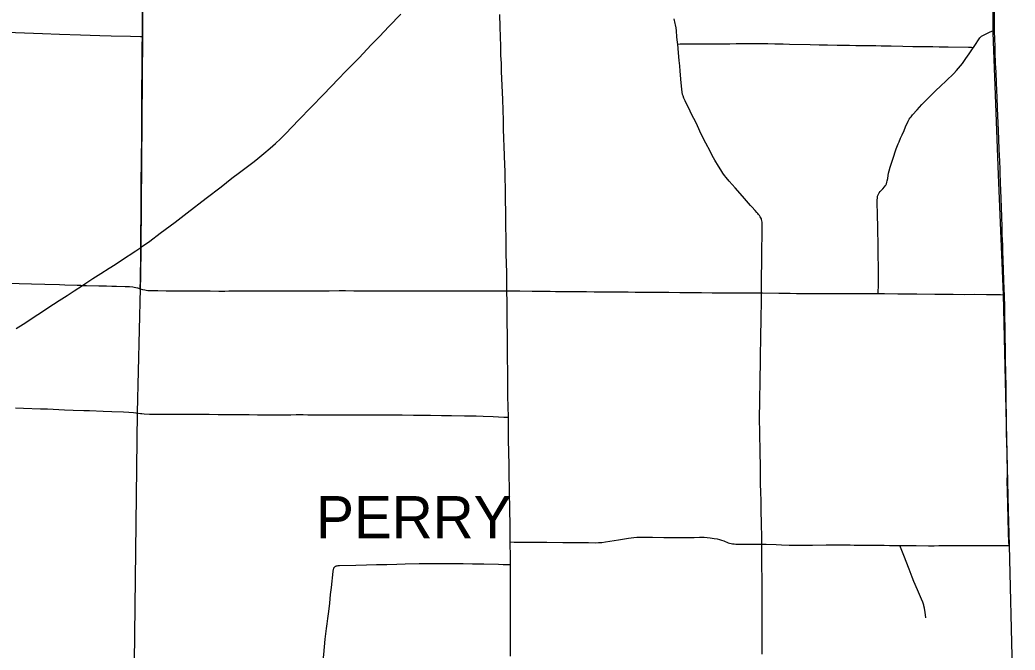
# Model space of a CAD drawing. Extents: x 1815539 to 1947826, y 273303 to 993194.
# Drawn here: x 1913070 to 1934195, y 939932 to 953318 of the extents above; entities that cross this region are included whole.
import ezdxf

# ---------------------------------------------------------------- set-up
doc = ezdxf.new("R2010")
doc.units = 0
for name, color, linetype in [('GM_X_County', 7, 'Continuous'), ('GM_X_County_Road', 7, 'Continuous'), ('GM_X_State_Route', 7, 'Continuous'), ('GM_X_Township', 7, 'Continuous'), ('GM_X_Township_Road', 7, 'Continuous'), ('GM_X_Township_Text', 7, 'Continuous'), ('GM_X_US_Route', 7, 'Continuous')]:
    doc.layers.add(name, color=color, linetype=linetype)

msp = doc.modelspace()

# ---------------------------------------------------------------- linework, layer by layer
at = {"layer": 'GM_X_County'}
msp.add_lwpolyline([(1928357, 965797), (1928425, 962614), (1928467, 960653), (1930020, 960674), (1933801, 960656), (1933723, 955963), (1933713, 955812), (1933717, 954747), (1933720, 953054), (1933836, 950026), (1933939, 947488), (1934048, 942901), (1934067, 942157), (1934195, 936859)], dxfattribs=at)
at = {"layer": 'GM_X_County_Road'}
for points in [[(1915670, 952967), (1915670, 952983), (1915670, 953098), (1915673, 953312), (1915675, 953525), (1915676, 953755), (1915681, 954215), (1915682, 954412), (1915683, 954576), (1915683, 954707), (1915686, 955036), (1915690, 955266), (1915691, 955430), (1915693, 955551), (1915693, 955599)], [(1915635, 948484), (1915639, 948648), (1915640, 948829), (1915642, 949108), (1915644, 949371), (1915645, 949568), (1915644, 949699), (1915644, 949830), (1915646, 950011), (1915648, 950159), (1915649, 950274), (1915653, 950405), (1915655, 950783), (1915656, 951013), (1915656, 951259), (1915658, 951456), (1915659, 951670), (1915660, 951883), (1915663, 952212), (1915665, 952474), (1915667, 952753), (1915670, 952967)], [(1915625, 947609), (1915626, 947637), (1915627, 947775), (1915630, 947972), (1915635, 948153), (1915637, 948269), (1915636, 948351), (1915636, 948466), (1915635, 948484)], [(1910365, 947816), (1910498, 947813), (1910842, 947800), (1911137, 947790), (1911350, 947783), (1911580, 947775), (1911744, 947768), (1911941, 947760), (1912104, 947754), (1912301, 947748), (1912662, 947734), (1913055, 947722), (1913318, 947713), (1913597, 947703), (1913908, 947695), (1914023, 947692), (1914285, 947685), (1914367, 947681), (1914402, 947680)], [(1914402, 947680), (1914482, 947679), (1914744, 947673), (1914908, 947667), (1915023, 947663), (1915121, 947662), (1915302, 947656), (1915400, 947652), (1915466, 947647), (1915498, 947643), (1915531, 947637), (1915563, 947629), (1915625, 947609)], [(1915625, 947609), (1915673, 947595), (1915720, 947583), (1915752, 947577), (1915784, 947572), (1915833, 947569), (1915997, 947567), (1916177, 947565), (1916292, 947565), (1916390, 947564), (1916571, 947563), (1916669, 947562), (1916932, 947560), (1917112, 947560), (1917292, 947559), (1917423, 947559), (1917505, 947560), (1917604, 947562), (1917702, 947562), (1917800, 947561), (1917866, 947560), (1917931, 947560), (1918062, 947561), (1918111, 947561), (1918325, 947563), (1918407, 947563), (1918571, 947564), (1918685, 947563), (1918800, 947564), (1918882, 947564), (1919259, 947564), (1919358, 947564), (1919473, 947565), (1919554, 947565), (1919636, 947566), (1919850, 947567), (1919981, 947567), (1920161, 947566), (1920489, 947563), (1920637, 947565), (1920735, 947566), (1921063, 947564), (1921260, 947562), (1921408, 947564), (1921506, 947564), (1921621, 947562), (1921702, 947562), (1921816, 947562), (1921948, 947563), (1922128, 947563), (1922341, 947561), (1922456, 947562), (1922718, 947563), (1923047, 947563), (1923226, 947563), (1923372, 947561), (1923409, 947561)], [(1923409, 947561), (1923536, 947562), (1923684, 947562), (1923946, 947559), (1924077, 947557), (1924209, 947556), (1924323, 947554), (1924438, 947552), (1924569, 947552), (1924733, 947550), (1924799, 947550), (1924995, 947547), (1925094, 947546), (1925258, 947545), (1925405, 947544), (1925651, 947543), (1925815, 947540), (1925979, 947539), (1926127, 947537), (1926274, 947536), (1926389, 947536), (1926504, 947536), (1926652, 947533), (1926848, 947533), (1927078, 947531), (1927258, 947529), (1927390, 947527), (1927537, 947527), (1927767, 947524), (1927947, 947523), (1928029, 947523), (1928226, 947522), (1928603, 947519), (1928814, 947518)], [(1928814, 947518), (1928833, 947518), (1929178, 947515), (1929325, 947513), (1929424, 947512), (1929555, 947510), (1929653, 947510), (1929801, 947509), (1930080, 947506), (1930309, 947506), (1930555, 947507), (1930654, 947508), (1930851, 947509), (1931047, 947507), (1931244, 947506), (1931286, 947506)], [(1931286, 947506), (1931425, 947505), (1931704, 947502), (1931981, 947499), (1932112, 947499), (1932489, 947494), (1932882, 947492), (1933112, 947489), (1933341, 947490), (1933587, 947488), (1933882, 947482), (1933932, 947480), (1933967, 947479)]]:
    msp.add_lwpolyline(points, dxfattribs=at)
at = {"layer": 'GM_X_State_Route'}
for points in [[(1923416, 946828), (1923415, 946875), (1923414, 947039), (1923414, 947203), (1923412, 947367), (1923409, 947515), (1923409, 947561), (1923408, 947646), (1923406, 947777), (1923403, 947925), (1923399, 948171), (1923395, 948319), (1923393, 948466), (1923390, 948646), (1923386, 948974), (1923384, 949122), (1923382, 949286), (1923381, 949450), (1923375, 949745), (1923372, 949958), (1923368, 950089), (1923358, 950417), (1923350, 950647), (1923345, 950778), (1923338, 951024), (1923333, 951188), (1923326, 951401), (1923318, 951630), (1923295, 952220), (1923290, 952401), (1923282, 952565), (1923276, 952761), (1923269, 952958), (1923263, 953171), (1923256, 953433)], [(1923442, 944632), (1923443, 944695), (1923440, 944875), (1923440, 944880), (1923434, 945105), (1923431, 945318), (1923429, 945481), (1923427, 945662), (1923425, 945809), (1923425, 945941), (1923423, 946039), (1923422, 946170), (1923420, 946416), (1923417, 946695), (1923416, 946828)], [(1923486, 939807), (1923485, 940021), (1923485, 940168), (1923485, 940513), (1923485, 940660), (1923485, 940906), (1923484, 941152), (1923483, 941431), (1923483, 941611), (1923483, 941752), (1923482, 941923), (1923479, 942202), (1923478, 942230), (1923475, 942579), (1923468, 942924), (1923467, 943022), (1923466, 943186), (1923462, 943383), (1923457, 943629), (1923453, 943858), (1923448, 944137), (1923443, 944400), (1923442, 944596), (1923442, 944632)]]:
    msp.add_lwpolyline(points, dxfattribs=at)
at = {"layer": 'GM_X_Township'}
msp.add_lwpolyline([(1889423, 961536), (1894728, 961453), (1894730, 961440), (1894815, 961451), (1899962, 961375), (1907847, 961159), (1910485, 961083), (1915744, 960965), (1915744, 960672), (1915689, 955598), (1915669, 952972), (1915640, 948490), (1915630, 947868), (1915624, 947610), (1915561, 944982), (1915495, 939674)], dxfattribs=at)
at = {"layer": 'GM_X_Township_Road'}
for points in [[(1933760, 953098), (1933758, 953287), (1933757, 953402), (1933754, 953582), (1933754, 953664), (1933751, 953762), (1933744, 954041), (1933740, 954221), (1933734, 954451), (1933730, 954615), (1933723, 954828), (1933719, 954910), (1933717, 954972), (1933716, 955106), (1933717, 955171), (1933717, 955237), (1933721, 955434), (1933723, 955581), (1933729, 955762), (1933730, 955808)], [(1927033, 952806), (1927029, 952841), (1927018, 952955), (1927005, 953084), (1926998, 953149), (1926988, 953212), (1926982, 953243), (1926959, 953338)], [(1910427, 953140), (1910699, 953130), (1910977, 953122), (1911371, 953109), (1911699, 953099), (1911977, 953091), (1912600, 953066), (1912715, 953060), (1912977, 953051), (1913551, 953030), (1913911, 953017), (1914354, 953002), (1914764, 952989), (1915010, 952982), (1915420, 952971), (1915633, 952967), (1915670, 952967)], [(1933309, 952730), (1933356, 952799), (1933420, 952894), (1933449, 952934), (1933470, 952959), (1933482, 952970), (1933495, 952980), (1933509, 952989), (1933538, 953004), (1933568, 953017), (1933667, 953062), (1933720, 953083), (1933760, 953098)], [(1933879, 950068), (1933876, 950143), (1933869, 950324), (1933864, 950438), (1933859, 950569), (1933843, 950979), (1933824, 951438), (1933813, 951683), (1933808, 951814), (1933800, 951994), (1933791, 952190), (1933785, 952320), (1933782, 952369), (1933777, 952451), (1933774, 952566), (1933770, 952779), (1933766, 952894), (1933760, 953090), (1933760, 953098)], [(1927033, 952806), (1927089, 952808), (1927137, 952807), (1927388, 952808), (1927536, 952810), (1927651, 952810), (1927782, 952811), (1927929, 952811), (1928027, 952813), (1928142, 952813), (1928273, 952815), (1928584, 952818), (1928699, 952817), (1928945, 952814), (1929092, 952811), (1929273, 952807), (1929404, 952803), (1929846, 952797), (1930037, 952792), (1930216, 952787), (1930419, 952779), (1930534, 952779), (1930681, 952779), (1930812, 952777), (1930943, 952775), (1931091, 952773), (1931173, 952772), (1931238, 952771), (1931353, 952770), (1931467, 952767), (1931565, 952765), (1931811, 952761), (1932024, 952755), (1932204, 952754), (1932303, 952754), (1932450, 952751), (1932581, 952748), (1932777, 952747), (1933204, 952741), (1933253, 952738), (1933271, 952738), (1933309, 952730)], [(1928814, 947518), (1928814, 947608), (1928815, 947741), (1928815, 947883), (1928818, 948145), (1928821, 948458), (1928826, 948737), (1928828, 948868), (1928827, 948982), (1928824, 949021), (1928822, 949050), (1928815, 949079), (1928809, 949095), (1928800, 949112), (1928787, 949138), (1928767, 949164), (1928748, 949188), (1928732, 949207), (1928712, 949229), (1928676, 949272), (1928606, 949350), (1928582, 949377), (1928493, 949477), (1928407, 949575), (1928252, 949750), (1928126, 949891), (1928063, 949972), (1928029, 950015), (1927993, 950064), (1927947, 950132), (1927899, 950210), (1927824, 950339), (1927768, 950440), (1927723, 950527), (1927631, 950700), (1927534, 950890), (1927452, 951069), (1927402, 951172), (1927351, 951275), (1927299, 951377), (1927192, 951598), (1927165, 951658), (1927147, 951705), (1927138, 951737), (1927129, 951785), (1927120, 951850), (1927108, 951981), (1927085, 952226), (1927076, 952339), (1927066, 952453), (1927059, 952534), (1927041, 952713), (1927033, 952806)], [(1932614, 951913), (1932730, 952024), (1932895, 952183), (1932952, 952242), (1932996, 952291), (1933038, 952341), (1933077, 952394), (1933153, 952500), (1933217, 952596), (1933291, 952704), (1933309, 952730)], [(1931286, 947506), (1931289, 947548), (1931291, 947564), (1931296, 947646), (1931297, 947712), (1931294, 947794), (1931293, 947859), (1931294, 947925), (1931295, 947974), (1931296, 948022), (1931295, 948070), (1931295, 948086), (1931295, 948102), (1931294, 948119), (1931294, 948134), (1931291, 948247), (1931290, 948295), (1931289, 948344), (1931288, 948393), (1931286, 948541), (1931280, 948869), (1931274, 949230), (1931270, 949394), (1931270, 949492), (1931273, 949541), (1931278, 949573), (1931283, 949589), (1931289, 949604), (1931295, 949619), (1931303, 949633), (1931312, 949647), (1931331, 949673), (1931352, 949698), (1931387, 949733), (1931420, 949769), (1931440, 949795), (1931448, 949809), (1931463, 949839), (1931474, 949869), (1931483, 949901), (1931492, 949949), (1931502, 950014), (1931511, 950062), (1931522, 950110), (1931545, 950189), (1931602, 950360), (1931674, 950578), (1931712, 950686), (1931731, 950731), (1931766, 950805), (1931800, 950880), (1931838, 950970), (1931871, 951045), (1931926, 951164), (1931949, 951208), (1931967, 951235), (1931986, 951262), (1932018, 951299), (1932117, 951409), (1932215, 951519), (1932259, 951567), (1932329, 951636), (1932412, 951716), (1932529, 951831), (1932599, 951899), (1932614, 951913)], [(1933967, 947479), (1933963, 947588), (1933959, 947802), (1933952, 947998), (1933941, 948228), (1933938, 948392), (1933932, 948539), (1933927, 948637), (1933921, 948768), (1933918, 948915), (1933911, 949144), (1933905, 949324), (1933898, 949537), (1933892, 949684), (1933886, 949865), (1933879, 950068)], [(1928819, 942182), (1928819, 942189), (1928817, 942376), (1928813, 942573), (1928809, 942737), (1928808, 942786), (1928806, 942884), (1928806, 942966), (1928803, 943147), (1928800, 943245), (1928794, 943507), (1928792, 943638), (1928789, 943786), (1928788, 943851), (1928788, 943950), (1928787, 944015), (1928783, 944212), (1928782, 944310), (1928778, 944375), (1928774, 944556), (1928773, 944851), (1928773, 944982), (1928775, 945098), (1928778, 945293), (1928784, 945605), (1928786, 945752), (1928788, 945982), (1928789, 946146), (1928794, 946310), (1928795, 946441), (1928798, 946556), (1928800, 946703), (1928803, 946850), (1928807, 947063), (1928812, 947260), (1928814, 947489), (1928814, 947518)], [(1934066, 942151), (1934064, 942235), (1934056, 942413), (1934053, 942510), (1934052, 942559), (1934050, 942608), (1934049, 942641), (1934049, 942690), (1934048, 942738), (1934047, 942786), (1934046, 942849), (1934045, 942865), (1934044, 942881), (1934040, 942995), (1934039, 943044), (1934039, 943094), (1934036, 943241), (1934035, 943323), (1934030, 943504), (1934031, 943684), (1934026, 944094), (1934019, 944373), (1934016, 944521), (1934013, 944718), (1934010, 944849), (1934007, 945259), (1934003, 945571), (1934000, 945768), (1933993, 946162), (1933990, 946326), (1933985, 946588), (1933982, 946736), (1933981, 946851), (1933980, 946949), (1933975, 947212), (1933967, 947479)], [(1912974, 945078), (1913149, 945072), (1913510, 945059), (1913658, 945054), (1913773, 945051), (1914019, 945039), (1914200, 945032), (1914429, 945023), (1914544, 945019), (1914840, 945010), (1915021, 945002), (1915267, 944993), (1915382, 944987), (1915480, 944979), (1915529, 944973), (1915538, 944971)], [(1915538, 944971), (1915632, 944959)], [(1915632, 944959), (1915659, 944955), (1915708, 944951), (1915823, 944947), (1915970, 944946), (1916085, 944946), (1916232, 944946), (1916429, 944943), (1916659, 944942), (1916855, 944942), (1917085, 944941), (1917281, 944938), (1917445, 944937), (1917740, 944937), (1917937, 944935), (1918117, 944933), (1918281, 944932), (1918527, 944933), (1918675, 944933), (1918822, 944933), (1918937, 944934), (1919084, 944934), (1919183, 944932), (1919281, 944932), (1919412, 944931), (1919527, 944931), (1919674, 944929), (1919805, 944929), (1920018, 944929), (1920199, 944930), (1920362, 944930), (1920608, 944930), (1920723, 944931), (1920838, 944931), (1921018, 944927), (1921182, 944928), (1921428, 944924), (1921788, 944922), (1922018, 944917), (1922231, 944915), (1922510, 944910), (1922755, 944906), (1922903, 944903), (1923116, 944893), (1923345, 944883), (1923411, 944881), (1923440, 944880)], [(1923478, 942230), (1923563, 942227), (1923662, 942226), (1923810, 942227), (1923990, 942226), (1924122, 942224), (1924253, 942222), (1924598, 942221), (1924828, 942218), (1924992, 942216), (1925140, 942215), (1925288, 942213), (1925354, 942215), (1925420, 942221), (1925501, 942232), (1925777, 942275), (1925988, 942307), (1926102, 942323), (1926167, 942329), (1926233, 942331), (1926348, 942332), (1926495, 942329), (1926742, 942324), (1926873, 942323), (1927103, 942323), (1927202, 942324), (1927382, 942326), (1927497, 942328), (1927596, 942328), (1927661, 942325), (1927726, 942318), (1927807, 942306), (1927871, 942293), (1927919, 942282), (1927966, 942268), (1928012, 942251), (1928103, 942213), (1928135, 942203), (1928167, 942195), (1928199, 942189), (1928232, 942186), (1928265, 942184), (1928430, 942185), (1928659, 942183), (1928819, 942182)], [(1928829, 939845), (1928829, 939960), (1928829, 940139), (1928829, 940238), (1928827, 940434), (1928826, 940533), (1928826, 940647), (1928825, 940811), (1928825, 940941), (1928826, 941187), (1928825, 941318), (1928825, 941432), (1928823, 941530), (1928822, 941629), (1928821, 941741), (1928820, 941888), (1928820, 942068), (1928819, 942182)], [(1928819, 942182), (1928912, 942180), (1929124, 942173), (1929239, 942169), (1929402, 942164), (1929550, 942160), (1929648, 942158), (1929746, 942158), (1929893, 942160), (1930187, 942166), (1930378, 942171), (1930492, 942171), (1930594, 942168), (1930694, 942167), (1930776, 942163), (1930842, 942162), (1930940, 942164), (1930989, 942164), (1931070, 942164), (1931267, 942162), (1931414, 942160), (1931528, 942157), (1931752, 942154)], [(1931752, 942154), (1931866, 942154), (1931948, 942153), (1932096, 942152), (1932360, 942150), (1932475, 942150), (1932574, 942151), (1932688, 942152), (1932918, 942152), (1933115, 942151), (1933230, 942152), (1933345, 942152), (1933444, 942152), (1933641, 942151), (1933822, 942151), (1934066, 942151)], [(1932257, 940886), (1932252, 940906), (1932236, 940952), (1932211, 941013), (1932123, 941209), (1932047, 941391), (1932010, 941483), (1931946, 941652), (1931833, 941944), (1931752, 942154)], [(1919769, 941713), (1919779, 941718), (1919793, 941722), (1919808, 941725), (1919824, 941726), (1919857, 941728), (1920201, 941734), (1920430, 941742), (1920643, 941747), (1920856, 941752), (1921069, 941760), (1921249, 941766), (1921544, 941771), (1921642, 941772), (1921888, 941775), (1922117, 941775), (1922478, 941772), (1922674, 941767), (1922920, 941764), (1923232, 941757), (1923330, 941753), (1923412, 941751), (1923483, 941752)], [(1919490, 939617), (1919501, 939677), (1919506, 939711), (1919519, 939840), (1919535, 940003), (1919553, 940166), (1919567, 940280), (1919581, 940394), (1919594, 940492), (1919607, 940606), (1919626, 940753), (1919646, 940932), (1919666, 941112), (1919682, 941259), (1919720, 941602), (1919727, 941650), (1919731, 941665), (1919737, 941680), (1919746, 941692), (1919760, 941706), (1919769, 941713)], [(1932300, 940615), (1932293, 940681), (1932286, 940729), (1932270, 940826), (1932261, 940874), (1932257, 940886)]]:
    msp.add_lwpolyline(points, dxfattribs=at)
at = {"layer": 'GM_X_US_Route'}
msp.add_lwpolyline([(1912994, 946763), (1913136, 946855), (1913453, 947060), (1913782, 947277), (1913906, 947357), (1914071, 947465), (1914222, 947563), (1914402, 947680), (1914470, 947725), (1914621, 947822), (1914787, 947929), (1914965, 948046), (1915090, 948124), (1915229, 948213), (1915530, 948411), (1915635, 948484), (1915652, 948495), (1915825, 948620), (1916048, 948787), (1916364, 949023), (1916624, 949223), (1917027, 949534), (1917339, 949774), (1917572, 949955), (1917729, 950074), (1917898, 950204), (1918043, 950312), (1918121, 950372), (1918247, 950477), (1918385, 950594), (1918495, 950692), (1918602, 950794), (1918708, 950898), (1918993, 951193), (1919254, 951465), (1919517, 951737), (1919835, 952068), (1919984, 952221), (1920120, 952363), (1920269, 952515), (1920528, 952789), (1920701, 952965), (1920905, 953178), (1921156, 953438)], dxfattribs=at)

# ---------------------------------------------------------------- texts
at = {"layer": 'GM_X_Township_Text'}
msp.add_text('PERRY', height=900, rotation=0, dxfattribs=at).set_placement((1919359, 942304))

doc.saveas('drawing.dxf')
